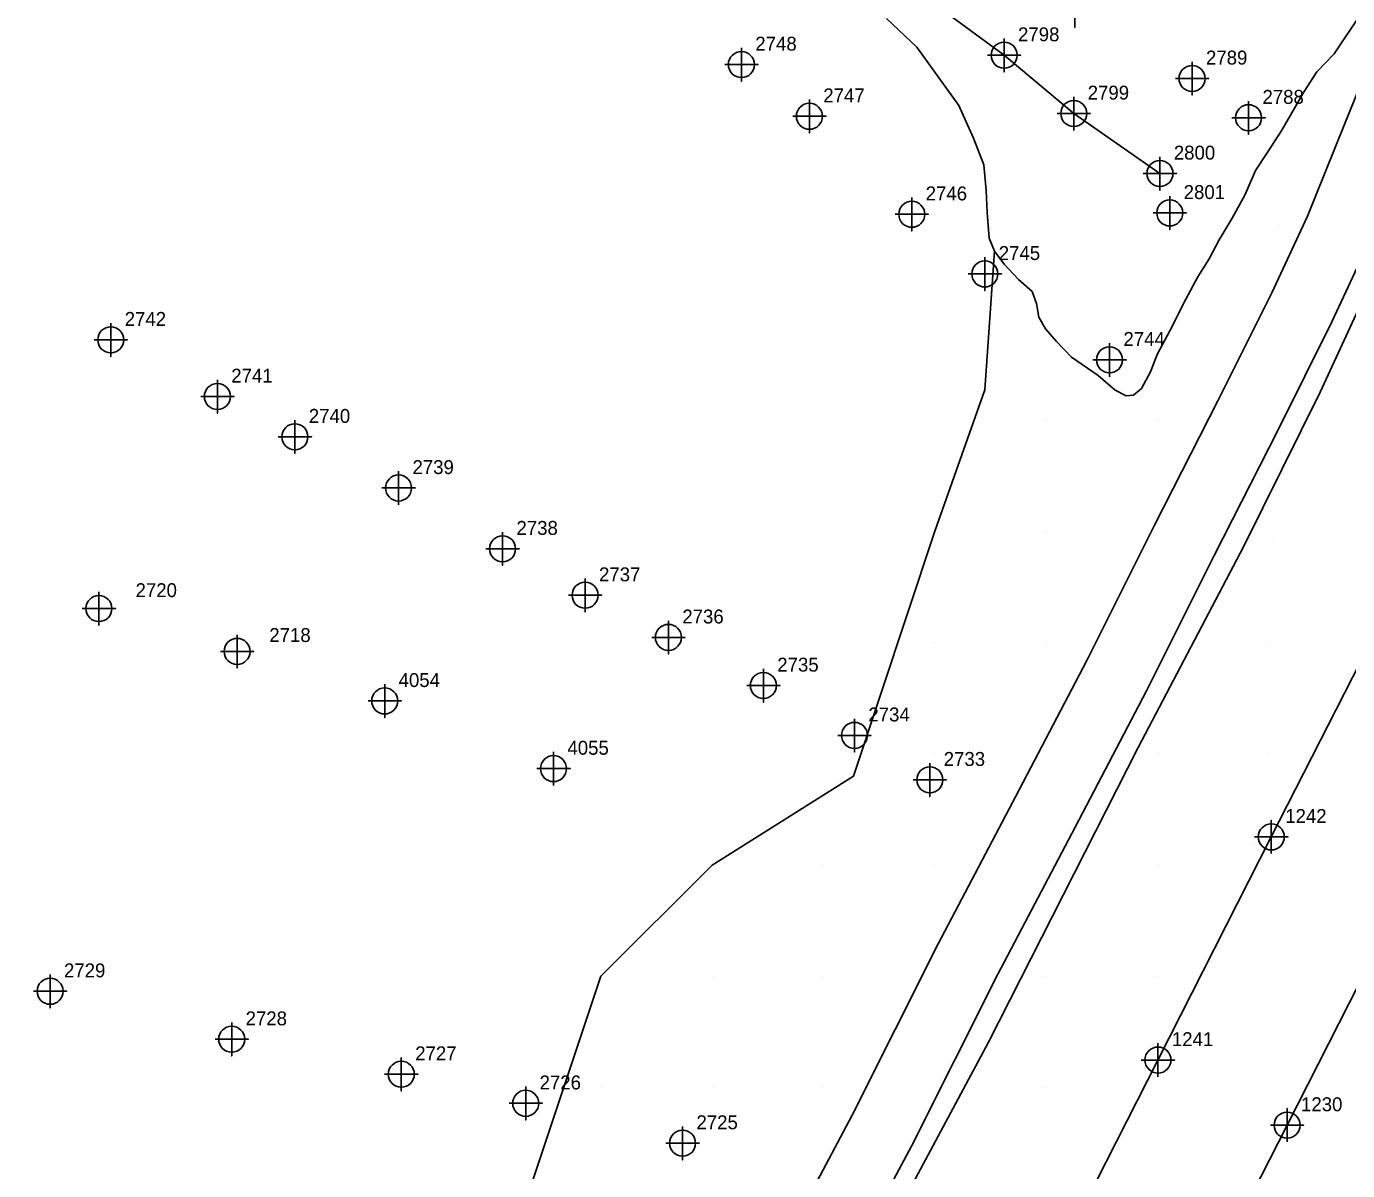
# Model space of a CAD drawing. Extents: x 2062781 to 2066835, y 358981 to 366501.
# Drawn here: x 2064535.6 to 2064773.1, y 362784.8 to 362990.5 of the extents above; entities that cross this region are included whole.
import ezdxf

# ---------------------------------------------------------------- set-up
doc = ezdxf.new("R2010")
doc.units = 0
for name, color, linetype in [('Exist DTM Regular Point CELL', 7, 'Continuous'), ('Exist DTM Regular Point Cogo Number', 7, 'Continuous'), ('Exist DTM Regular Point Underwater CELL', 7, 'Continuous'), ('Exist DTM Regular Point Underwater Cogo Number', 7, 'Continuous'), ('Exist Hydro Stream or Body of Water', 7, 'Continuous'), ('Exist Hydro Stream or Body of Water Cogo Number', 7, 'Continuous'), ('Exist Hydro Stream or Body of Water Cogo Point CELL', 7, 'Continuous'), ('Exist Structure Major Deck Tunnel Box Culvert', 7, 'Continuous'), ('Exist Structure Major Deck Tunnel Box Culvert Cogo Number', 7, 'Continuous'), ('Exist Structure Major Deck Tunnel Box Culvert Cogo Point CELL', 7, 'Continuous'), ('PH Exist DTM Breakline', 7, 'Continuous'), ('PH Exist DTM Point', 7, 'Continuous')]:
    doc.layers.add(name, color=color, linetype=linetype)

msp = doc.modelspace()

# ---------------------------------------------------------------- linework, layer by layer
at = {"layer": 'Exist DTM Regular Point CELL'}
for points in [[(2064664.12, 362986.62), (2064664.12, 362980.62), (2064664.12, 362983.62), (2064667.12, 362983.62), (2064661.12, 362983.62)], [(2064676.34, 362977.32), (2064676.34, 362971.32), (2064676.34, 362974.32), (2064679.34, 362974.32), (2064673.34, 362974.32)], [(2064694.74, 362959.71), (2064694.74, 362953.71), (2064694.74, 362956.71), (2064697.74, 362956.71), (2064691.74, 362956.71)], [(2064741.11, 362959.95), (2064741.11, 362953.95), (2064741.11, 362956.95), (2064744.11, 362956.95), (2064738.11, 362956.95)], [(2064707.87, 362948.99), (2064707.87, 362942.99), (2064707.87, 362945.99), (2064710.87, 362945.99), (2064704.87, 362945.99)], [(2064550.78, 362937.15), (2064550.78, 362931.15), (2064550.78, 362934.15), (2064553.78, 362934.15), (2064547.78, 362934.15)], [(2064730.28, 362933.55), (2064730.28, 362927.55), (2064730.28, 362930.55), (2064733.28, 362930.55), (2064727.28, 362930.55)], [(2064569.94, 362926.96), (2064569.94, 362920.96), (2064569.94, 362923.96), (2064572.94, 362923.96), (2064566.94, 362923.96)], [(2064583.87, 362919.72), (2064583.87, 362913.72), (2064583.87, 362916.72), (2064586.87, 362916.72), (2064580.87, 362916.72)], [(2064602.5, 362910.52), (2064602.5, 362904.52), (2064602.5, 362907.52), (2064605.5, 362907.52), (2064599.5, 362907.52)], [(2064621.19, 362899.59), (2064621.19, 362893.59), (2064621.19, 362896.59), (2064624.19, 362896.59), (2064618.19, 362896.59)], [(2064636.03, 362891.25), (2064636.03, 362885.25), (2064636.03, 362888.25), (2064639.03, 362888.25), (2064633.03, 362888.25)], [(2064548.64, 362888.85), (2064548.64, 362882.85), (2064548.64, 362885.85), (2064551.64, 362885.85), (2064545.64, 362885.85)], [(2064651, 362883.67), (2064651, 362877.67), (2064651, 362880.67), (2064654, 362880.67), (2064648, 362880.67)], [(2064573.48, 362881.15), (2064573.48, 362875.15), (2064573.48, 362878.15), (2064576.48, 362878.15), (2064570.48, 362878.15)], [(2064668.07, 362875.02), (2064668.07, 362869.02), (2064668.07, 362872.02), (2064671.07, 362872.02), (2064665.07, 362872.02)], [(2064600.01, 362872.25), (2064600.01, 362866.25), (2064600.01, 362869.25), (2064603.01, 362869.25), (2064597.01, 362869.25)], [(2064684.44, 362866.06), (2064684.44, 362860.06), (2064684.44, 362863.06), (2064687.44, 362863.06), (2064681.44, 362863.06)], [(2064630.35, 362860.08), (2064630.35, 362854.08), (2064630.35, 362857.08), (2064633.35, 362857.08), (2064627.35, 362857.08)], [(2064697.98, 362858.07), (2064697.98, 362852.07), (2064697.98, 362855.07), (2064700.98, 362855.07), (2064694.98, 362855.07)], [(2064539.87, 362820.07), (2064539.87, 362814.07), (2064539.87, 362817.07), (2064542.87, 362817.07), (2064536.87, 362817.07)], [(2064572.51, 362811.45), (2064572.51, 362805.45), (2064572.51, 362808.45), (2064575.51, 362808.45), (2064569.51, 362808.45)], [(2064602.99, 362805.16), (2064602.99, 362799.16), (2064602.99, 362802.16), (2064605.99, 362802.16), (2064599.99, 362802.16)], [(2064625.35, 362799.93), (2064625.35, 362793.93), (2064625.35, 362796.93), (2064628.35, 362796.93), (2064622.35, 362796.93)], [(2064653.54, 362792.77), (2064653.54, 362786.77), (2064653.54, 362789.77), (2064656.54, 362789.77), (2064650.54, 362789.77)]]:
    msp.add_lwpolyline(points, dxfattribs=at)
for centre in [(2064664.12, 362983.62), (2064676.34, 362974.32), (2064694.74, 362956.71), (2064741.11, 362956.95), (2064707.87, 362945.99), (2064550.78, 362934.15), (2064730.28, 362930.55), (2064569.94, 362923.96), (2064583.87, 362916.72), (2064602.5, 362907.52), (2064621.19, 362896.59), (2064636.03, 362888.25), (2064548.64, 362885.85), (2064651, 362880.67), (2064573.48, 362878.15), (2064668.07, 362872.02), (2064600.01, 362869.25), (2064684.44, 362863.06), (2064630.35, 362857.08), (2064697.98, 362855.07), (2064539.87, 362817.07), (2064572.51, 362808.45), (2064602.99, 362802.16), (2064625.35, 362796.93), (2064653.54, 362789.77)]:
    msp.add_circle(centre, 2.34, dxfattribs=at)
at = {"layer": 'Exist DTM Regular Point Underwater CELL'}
for points in [[(2064724.06, 362996.29), (2064724.06, 362990.29), (2064724.06, 362993.29), (2064727.06, 362993.29), (2064721.06, 362993.29)], [(2064745.12, 362984.12), (2064745.12, 362978.12), (2064745.12, 362981.12), (2064748.12, 362981.12), (2064742.12, 362981.12)], [(2064755.27, 362977.06), (2064755.27, 362971.06), (2064755.27, 362974.06), (2064758.27, 362974.06), (2064752.27, 362974.06)]]:
    msp.add_lwpolyline(points, dxfattribs=at)
for centre in [(2064745.12, 362981.12), (2064755.27, 362974.06)]:
    msp.add_circle(centre, 2.34, dxfattribs=at)
at = {"layer": 'Exist Hydro Stream or Body of Water'}
msp.add_lwpolyline([(2064617.98, 363043.42), (2064639.91, 363030.5), (2064657.69, 363031.04), (2064682, 363006.89), (2064711.34, 362985.3), (2064723.86, 362974.82), (2064739.34, 362964.04)], dxfattribs=at)
at = {"layer": 'Exist Hydro Stream or Body of Water Cogo Point CELL'}
for points in [[(2064708.34, 362985.3), (2064714.34, 362985.3), (2064711.34, 362985.3), (2064711.34, 362982.3), (2064711.34, 362988.3)], [(2064708.34, 362985.3), (2064714.34, 362985.3), (2064711.34, 362985.3), (2064711.34, 362982.3), (2064711.34, 362988.3)], [(2064708.34, 362985.3), (2064714.34, 362985.3), (2064711.34, 362985.3), (2064711.34, 362982.3), (2064711.34, 362988.3)], [(2064720.86, 362974.82), (2064726.86, 362974.82), (2064723.86, 362974.82), (2064723.86, 362971.82), (2064723.86, 362977.82)], [(2064720.86, 362974.82), (2064726.86, 362974.82), (2064723.86, 362974.82), (2064723.86, 362971.82), (2064723.86, 362977.82)], [(2064720.86, 362974.82), (2064726.86, 362974.82), (2064723.86, 362974.82), (2064723.86, 362971.82), (2064723.86, 362977.82)], [(2064736.34, 362964.04), (2064742.34, 362964.04), (2064739.34, 362964.04), (2064739.34, 362961.04), (2064739.34, 362967.04)], [(2064736.34, 362964.04), (2064742.34, 362964.04), (2064739.34, 362964.04), (2064739.34, 362961.04), (2064739.34, 362967.04)], [(2064736.34, 362964.04), (2064742.34, 362964.04), (2064739.34, 362964.04), (2064739.34, 362961.04), (2064739.34, 362967.04)]]:
    msp.add_lwpolyline(points, dxfattribs=at)
for centre in [(2064711.34, 362985.3), (2064711.34, 362985.3), (2064711.34, 362985.3), (2064723.86, 362974.82), (2064723.86, 362974.82), (2064723.86, 362974.82), (2064739.34, 362964.04), (2064739.34, 362964.04), (2064739.34, 362964.04)]:
    msp.add_circle(centre, 2.34, dxfattribs=at)
at = {"layer": 'Exist Structure Major Deck Tunnel Box Culvert'}
for points in [[(2064623.4, 362577.44), (2064650.62, 362630.92), (2064677.82, 362684.31), (2064698.23, 362724.56), (2064718.6, 362764.59), (2064738.99, 362804.71), (2064759.36, 362844.81), (2064779.84, 362884.94), (2064800.12, 362924.98), (2064820.56, 362965.07), (2064840.94, 363005.22), (2064861.36, 363045.25), (2064881.68, 363085.34), (2064902.1, 363125.46), (2064922.64, 363165.68)], [(2064945.77, 363153.79), (2064925.42, 363113.93), (2064904.9, 363073.71), (2064884.54, 363033.52), (2064864.2, 362993.6), (2064843.79, 362953.32), (2064823.4, 362913.38), (2064803.04, 362873.21), (2064782.63, 362833.19), (2064762.2, 362793.01), (2064741.73, 362752.83), (2064721.36, 362712.82), (2064700.92, 362672.65), (2064673.77, 362619.11), (2064646.54, 362565.66)]]:
    msp.add_lwpolyline(points, dxfattribs=at)
at = {"layer": 'Exist Structure Major Deck Tunnel Box Culvert Cogo Point CELL'}
for points in [[(2064756.36, 362844.81), (2064762.36, 362844.81), (2064759.36, 362844.81), (2064759.36, 362847.81), (2064759.36, 362841.81)], [(2064756.36, 362844.81), (2064762.36, 362844.81), (2064759.36, 362844.81), (2064759.36, 362847.81), (2064759.36, 362841.81)], [(2064756.36, 362844.81), (2064762.36, 362844.81), (2064759.36, 362844.81), (2064759.36, 362847.81), (2064759.36, 362841.81)], [(2064735.99, 362804.71), (2064741.99, 362804.71), (2064738.99, 362804.71), (2064738.99, 362807.71), (2064738.99, 362801.71)], [(2064735.99, 362804.71), (2064741.99, 362804.71), (2064738.99, 362804.71), (2064738.99, 362807.71), (2064738.99, 362801.71)], [(2064735.99, 362804.71), (2064741.99, 362804.71), (2064738.99, 362804.71), (2064738.99, 362807.71), (2064738.99, 362801.71)], [(2064759.2, 362793.01), (2064765.2, 362793.01), (2064762.2, 362793.01), (2064762.2, 362796.01), (2064762.2, 362790.01)], [(2064759.2, 362793.01), (2064765.2, 362793.01), (2064762.2, 362793.01), (2064762.2, 362796.01), (2064762.2, 362790.01)], [(2064759.2, 362793.01), (2064765.2, 362793.01), (2064762.2, 362793.01), (2064762.2, 362796.01), (2064762.2, 362790.01)]]:
    msp.add_lwpolyline(points, dxfattribs=at)
for centre in [(2064759.36, 362844.81), (2064759.36, 362844.81), (2064759.36, 362844.81), (2064738.99, 362804.71), (2064738.99, 362804.71), (2064738.99, 362804.71), (2064762.2, 362793.01), (2064762.2, 362793.01), (2064762.2, 362793.01)]:
    msp.add_circle(centre, 2.34, dxfattribs=at)
at = {"layer": 'PH Exist DTM Breakline'}
for points in [[(2064807.3, 363030.11), (2064802.32, 363011.11), (2064797.84, 362995.47), (2064791.78, 362977.67), (2064781.44, 362953.56), (2064768.13, 362924.72), (2064754.4, 362897.09), (2064735.4, 362860.89), (2064708.55, 362807.94), (2064678.24, 362751.31), (2064659.16, 362714.52), (2064643.7, 362686.38), (2064628.13, 362658.09), (2064617.21, 362639.02), (2064609.98, 362625.86), (2064598.02, 362605.33), (2064591.98, 362596.35), (2064587.07, 362588.82), (2064583.37, 362583.25)], [(2064785.71, 363007.19), (2064779.45, 362990.06), (2064772.48, 362972.75), (2064765.86, 362956.39), (2064759.45, 362942.62), (2064749.79, 362923.28), (2064738.37, 362900.81), (2064726.23, 362876.54), (2064713.46, 362852.12), (2064699.51, 362825.61), (2064684.05, 362794.78), (2064670.4, 362769.18), (2064655.54, 362741.04), (2064646.23, 362723.48), (2064637.14, 362706.29), (2064626.33, 362686.94), (2064613.68, 362664.82), (2064602.29, 362645.78), (2064593.55, 362632.4), (2064584.44, 362619.51), (2064571.75, 362603.76), (2064561.33, 362592.06)], [(2064797.04, 363003.22), (2064790.66, 362985.76), (2064783.61, 362968.25), (2064776.87, 362951.61), (2064770.26, 362937.41), (2064760.51, 362917.88), (2064749.09, 362895.41), (2064736.91, 362871.07), (2064724.09, 362846.54), (2064710.18, 362820.13), (2064694.71, 362789.26), (2064681, 362763.56), (2064666.15, 362735.42), (2064656.83, 362717.87), (2064647.69, 362700.56), (2064636.78, 362681.03), (2064624.04, 362658.76), (2064612.46, 362639.42), (2064603.47, 362625.65), (2064594.02, 362612.27), (2064580.91, 362596.01), (2064570.29, 362584.08)], [(2064775.49, 362992.81), (2064770.64, 362985.56), (2064767.55, 362982.29), (2064765.25, 362978.76), (2064761.25, 362971.85), (2064758.64, 362967.76), (2064756.54, 362964.58), (2064754.67, 362960.27), (2064752.3, 362955.99), (2064749.97, 362952.12), (2064748.2, 362948.68), (2064746.18, 362945.45), (2064743.98, 362941.44), (2064741.21, 362935.86), (2064738.86, 362931.49), (2064737.62, 362928.37), (2064736.01, 362925.4), (2064734.59, 362924.23), (2064733.3, 362924.11), (2064731.28, 362925.11), (2064728.24, 362927.71), (2064723.45, 362931.03), (2064720.73, 362933.86), (2064718.76, 362936.1), (2064717.57, 362938.23), (2064717.15, 362940.7), (2064716.35, 362942.81), (2064713.94, 362944.97), (2064711.32, 362947.75), (2064709.63, 362950.09), (2064708.67, 362952.44), (2064708.27, 362957.05), (2064708.11, 362960.97), (2064707.72, 362965.62), (2064705.83, 362970.37), (2064703.18, 362976.28), (2064698.58, 362982.65), (2064695.66, 362986.75), (2064690.17, 362991.9)], [(2064709.63, 362950.09), (2064707.87, 362925.16), (2064698.86, 362899.76), (2064684.28, 362855.7), (2064658.86, 362839.76), (2064638.86, 362819.76), (2064618.86, 362759.76), (2064598.86, 362739.76), (2064578.84, 362699.72), (2064538.86, 362699.76), (2064478.86, 362679.76), (2064478.93, 362700.07), (2064458.86, 362739.76), (2064438.86, 362739.76), (2064418.86, 362739.76), (2064393.6, 362752.5)]]:
    msp.add_lwpolyline(points, dxfattribs=at)
at = {"layer": 'PH Exist DTM Point'}
for p, q in [((2064760.66, 362954.84), (2064760.66, 362954.84)), ((2064718.86, 362919.76), (2064718.86, 362919.76)), ((2064738.86, 362919.76), (2064738.86, 362919.76)), ((2064718.86, 362899.76), (2064718.86, 362899.76)), ((2064759.7, 362898.04), (2064759.7, 362898.04)), ((2064698.86, 362879.76), (2064698.86, 362879.76)), ((2064718.86, 362879.76), (2064718.86, 362879.76)), ((2064758.86, 362879.76), (2064758.86, 362879.76)), ((2064698.86, 362859.76), (2064698.86, 362859.76)), ((2064738.86, 362859.76), (2064738.86, 362859.76)), ((2064758.84, 362859.72), (2064758.84, 362859.72)), ((2064756.16, 362843.67), (2064756.16, 362843.67)), ((2064678.86, 362839.76), (2064678.86, 362839.76)), ((2064698.86, 362839.76), (2064698.86, 362839.76)), ((2064738.86, 362839.76), (2064738.86, 362839.76)), ((2064658.86, 362819.76), (2064658.86, 362819.76)), ((2064678.86, 362819.76), (2064678.86, 362819.76)), ((2064718.86, 362819.76), (2064718.86, 362819.76)), ((2064738.86, 362819.76), (2064738.86, 362819.76)), ((2064638.86, 362799.76), (2064638.86, 362799.76)), ((2064658.86, 362799.76), (2064658.86, 362799.76)), ((2064678.86, 362799.76), (2064678.86, 362799.76)), ((2064718.86, 362799.76), (2064718.86, 362799.76))]:
    msp.add_line(p, q, dxfattribs=at)

# ---------------------------------------------------------------- texts
at = {"layer": 'Exist DTM Regular Point Cogo Number'}
for s, p in [('2748', (2064666.62, 362986.12)), ('2748', (2064666.62, 362986.12)), ('2748', (2064666.62, 362986.12)), ('2747', (2064678.84, 362976.82)), ('2747', (2064678.84, 362976.82)), ('2747', (2064678.84, 362976.82)), ('2746', (2064697.24, 362959.21)), ('2746', (2064697.24, 362959.21)), ('2746', (2064697.24, 362959.21)), ('2801', (2064743.61, 362959.45)), ('2801', (2064743.61, 362959.45)), ('2801', (2064743.61, 362959.45)), ('2745', (2064710.37, 362948.49)), ('2745', (2064710.37, 362948.49)), ('2745', (2064710.37, 362948.49)), ('2742', (2064553.28, 362936.65)), ('2742', (2064553.28, 362936.65)), ('2742', (2064553.28, 362936.65)), ('2744', (2064732.78, 362933.05)), ('2744', (2064732.78, 362933.05)), ('2744', (2064732.78, 362933.05)), ('2741', (2064572.44, 362926.46)), ('2741', (2064572.44, 362926.46)), ('2741', (2064572.44, 362926.46)), ('2740', (2064586.37, 362919.22)), ('2740', (2064586.37, 362919.22)), ('2740', (2064586.37, 362919.22)), ('2739', (2064605, 362910.02)), ('2739', (2064605, 362910.02)), ('2739', (2064605, 362910.02)), ('2738', (2064623.69, 362899.09)), ('2738', (2064623.69, 362899.09)), ('2738', (2064623.69, 362899.09)), ('2737', (2064638.53, 362890.75)), ('2737', (2064638.53, 362890.75)), ('2737', (2064638.53, 362890.75)), ('2720', (2064555.23, 362887.9)), ('2720', (2064555.23, 362887.9)), ('2720', (2064555.23, 362887.9)), ('2736', (2064653.5, 362883.17)), ('2736', (2064653.5, 362883.17)), ('2736', (2064653.5, 362883.17)), ('2718', (2064579.27, 362879.84)), ('2718', (2064579.27, 362879.84)), ('2718', (2064579.27, 362879.84)), ('2735', (2064670.57, 362874.52)), ('2735', (2064670.57, 362874.52)), ('2735', (2064670.57, 362874.52)), ('4054', (2064602.51, 362871.75)), ('4054', (2064602.51, 362871.75)), ('4054', (2064602.51, 362871.75)), ('2734', (2064686.94, 362865.56)), ('2734', (2064686.94, 362865.56)), ('2734', (2064686.94, 362865.56)), ('4055', (2064632.85, 362859.58)), ('4055', (2064632.85, 362859.58)), ('4055', (2064632.85, 362859.58)), ('2733', (2064700.48, 362857.57)), ('2733', (2064700.48, 362857.57)), ('2733', (2064700.48, 362857.57)), ('2729', (2064542.37, 362819.57)), ('2729', (2064542.37, 362819.57)), ('2729', (2064542.37, 362819.57)), ('2728', (2064575.01, 362810.95)), ('2728', (2064575.01, 362810.95)), ('2728', (2064575.01, 362810.95)), ('2727', (2064605.49, 362804.66)), ('2727', (2064605.49, 362804.66)), ('2727', (2064605.49, 362804.66)), ('2726', (2064627.85, 362799.43)), ('2726', (2064627.85, 362799.43)), ('2726', (2064627.85, 362799.43)), ('2725', (2064656.04, 362792.27)), ('2725', (2064656.04, 362792.27)), ('2725', (2064656.04, 362792.27))]:
    msp.add_text(s, height=2.5, dxfattribs=at).set_placement(p)
at = {"layer": 'Exist DTM Regular Point Underwater Cogo Number'}
for s, p in [('2789', (2064747.62, 362983.62)), ('2789', (2064747.62, 362983.62)), ('2789', (2064747.62, 362983.62)), ('2788', (2064757.77, 362976.56)), ('2788', (2064757.77, 362976.56)), ('2788', (2064757.77, 362976.56))]:
    msp.add_text(s, height=2.5, dxfattribs=at).set_placement(p)
at = {"layer": 'Exist Hydro Stream or Body of Water Cogo Number'}
for s, p in [('2798', (2064713.84, 362987.8)), ('2798', (2064713.84, 362987.8)), ('2798', (2064713.84, 362987.8)), ('2799', (2064726.36, 362977.32)), ('2799', (2064726.36, 362977.32)), ('2799', (2064726.36, 362977.32)), ('2800', (2064741.84, 362966.54)), ('2800', (2064741.84, 362966.54)), ('2800', (2064741.84, 362966.54))]:
    msp.add_text(s, height=2.5, dxfattribs=at).set_placement(p)
at = {"layer": 'Exist Structure Major Deck Tunnel Box Culvert Cogo Number'}
for s, p in [('1242', (2064761.86, 362847.31)), ('1242', (2064761.86, 362847.31)), ('1242', (2064761.86, 362847.31)), ('1241', (2064741.49, 362807.21)), ('1241', (2064741.49, 362807.21)), ('1241', (2064741.49, 362807.21)), ('1230', (2064764.7, 362795.51)), ('1230', (2064764.7, 362795.51)), ('1230', (2064764.7, 362795.51))]:
    msp.add_text(s, height=2.5, dxfattribs=at).set_placement(p)

doc.saveas('drawing.dxf')
